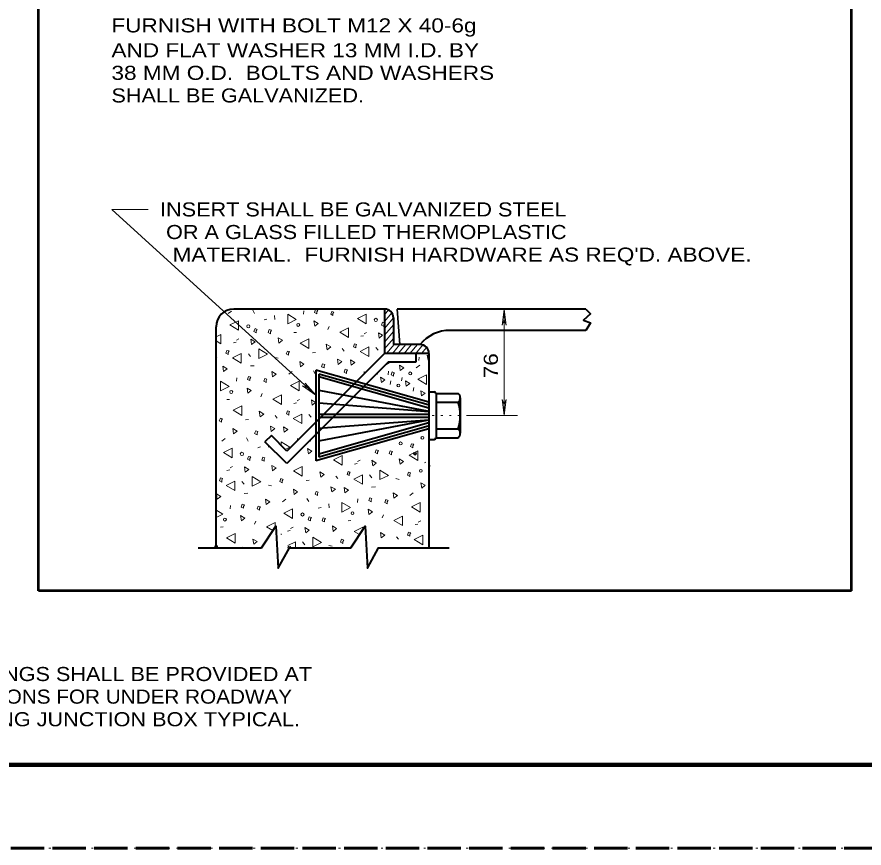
# Model space of a CAD drawing. Extents: x 312583 to 312854, y 144419 to 144597.
# Drawn here: x 312751.27 to 312797.02, y 144418.58 to 144463.44 of the extents above; entities that cross this region are included whole.
import ezdxf

# ---------------------------------------------------------------- set-up
doc = ezdxf.new("R2010")
doc.units = 0
doc.header["$LTSCALE"] = 0.3
doc.header["$PDMODE"] = 32
doc.header["$PDSIZE"] = 0.15
doc.linetypes.add('DOTTED', pattern=[1.5, 0.3, -1.2])
doc.linetypes.add('LONG_DASHED', pattern=[7.5, 6, -1.5])
doc.layers.add('1', color=7, linetype='Continuous', lineweight=13)
doc.layers.add('63', color=7, linetype='DOTTED', lineweight=13)

msp = doc.modelspace()

# ---------------------------------------------------------------- linework, layer by layer
at = {"layer": '1', "lineweight": 53}
for p, q in [((312796.3473, 144432.4767), (312796.3473, 144512.4926)), ((312752.4335, 144432.4767), (312752.4335, 144510.2401)), ((312796.3473, 144432.4767), (312752.4335, 144432.4767))]:
    msp.add_line(p, q, dxfattribs=at)
at = {"layer": '1'}
for p, q in [((312762.8669, 144447.5704), (312762.6829, 144447.4401)), ((312764.0169, 144447.6088), (312764.1013, 144447.4401)), ((312766.7463, 144447.3941), (312766.7693, 144447.5858)), ((312768.6936, 144447.6778), (312768.7013, 144447.6394)), ((312768.7013, 144447.6394), (312768.7549, 144447.6778)), ((312771.3463, 144447.6318), (312771.1316, 144447.3711)), ((312777.5793, 144447.6778), (312777.4719, 144446.8114)), ((312777.5793, 144441.9278), (312777.5793, 144447.6778)), ((312777.5793, 144447.6778), (312777.6866, 144446.8114)), ((312764.6226, 144447.0874), (312764.7683, 144447.1258)), ((312765.1823, 144447.3251), (312765.2053, 144447.1104)), ((312771.5226, 144447.4708), (312771.1316, 144447.0031)), ((312771.6069, 144447.2024), (312771.1316, 144446.6351)), ((312768.1416, 144446.7348), (312768.0649, 144446.5661)), ((312771.0933, 144446.8498), (312771.1316, 144446.9188)), ((312771.6069, 144446.8268), (312771.1316, 144446.2671)), ((312777.4719, 144446.8114), (312777.5793, 144447.0874)), ((312777.6866, 144446.8114), (312777.5793, 144447.0874)), ((312766.2326, 144446.4128), (312766.3783, 144446.4204)), ((312769.8513, 144446.2058), (312769.9969, 144446.2364)), ((312770.0199, 144446.3361), (312770.1503, 144446.4128)), ((312771.6069, 144446.4588), (312771.1316, 144445.8991)), ((312762.0313, 144445.9604), (312762.2919, 144445.7994)), ((312762.9666, 144445.8608), (312763.1123, 144445.8914)), ((312763.1353, 144445.9911), (312763.2579, 144446.0678)), ((312771.6069, 144446.0908), (312771.1316, 144445.5234)), ((312771.6453, 144445.7611), (312771.2389, 144445.2858)), ((312771.9596, 144445.7611), (312771.5533, 144445.2858)), ((312772.2739, 144445.7611), (312771.8676, 144445.2858)), ((312772.5883, 144445.7611), (312772.1819, 144445.2858)), ((312772.9026, 144445.7611), (312772.4963, 144445.2858)), ((312773.1939, 144445.7381), (312772.8106, 144445.2858)), ((312767.2446, 144445.3164), (312767.3979, 144445.3318)), ((312768.8469, 144445.5541), (312768.9543, 144445.4084)), ((312770.6563, 144445.6078), (312770.7789, 144445.4544)), ((312771.1316, 144445.4084), (312771.1239, 144445.4084)), ((312773.4009, 144445.6078), (312773.1249, 144445.2858)), ((312773.5159, 144445.3778), (312773.4393, 144445.2858)), ((312762.0313, 144445.1171), (312762.0619, 144445.0634)), ((312763.7716, 144445.2628), (312763.8943, 144445.1094)), ((312765.1976, 144445.0711), (312765.3739, 144445.0328)), ((312770.7713, 144444.9561), (312770.8019, 144444.9561)), ((312772.9716, 144444.9024), (312772.9946, 144445.0864)), ((312773.4776, 144444.9101), (312773.5313, 144444.9484)), ((312763.8866, 144444.6111), (312764.0936, 144444.6188)), ((312773.0253, 144444.6494), (312772.8413, 144444.5114)), ((312763.1276, 144443.7831), (312763.1506, 144443.9671)), ((312766.1329, 144444.3044), (312765.9566, 144444.1664)), ((312767.2829, 144444.3428), (312767.3749, 144444.1741)), ((312770.0199, 144444.1741), (312770.0353, 144444.3121)), ((312771.3156, 144444.1358), (312771.3386, 144444.3274)), ((312772.0516, 144443.7984), (312772.0746, 144443.9901)), ((312766.7003, 144443.5301), (312766.9763, 144443.4228)), ((312767.4133, 144443.0241), (312766.7003, 144443.5301)), ((312766.8459, 144443.6834), (312766.9763, 144443.4228)), ((312767.4133, 144443.0241), (312766.8459, 144443.6834)), ((312771.4383, 144443.6144), (312771.4613, 144443.8061)), ((312772.6803, 144443.2541), (312772.7033, 144443.4458)), ((312764.5229, 144443.1161), (312764.4463, 144442.9474)), ((312762.6139, 144442.8018), (312762.7596, 144442.8018)), ((312766.2326, 144442.5871), (312766.3783, 144442.6178)), ((312766.4089, 144442.7251), (312766.5316, 144442.7941)), ((312777.4719, 144442.7941), (312777.5793, 144442.5181)), ((312777.5793, 144441.9278), (312777.4719, 144442.7941)), ((312777.6866, 144442.7941), (312777.5793, 144442.5181)), ((312777.5793, 144441.9278), (312777.6866, 144442.7941)), ((312767.6049, 144442.2498), (312767.6049, 144441.7591)), ((312763.6259, 144441.6978), (312763.7793, 144441.7131)), ((312765.2283, 144441.9354), (312765.3356, 144441.7898)), ((312767.0376, 144441.9891), (312767.1603, 144441.8358)), ((312775.6473, 144441.9278), (312778.3076, 144441.9278)), ((312767.1603, 144441.3374), (312767.1909, 144441.3374)), ((312763.6719, 144440.7241), (312763.7563, 144440.5554)), ((312766.4089, 144440.5554), (312766.4243, 144440.6934)), ((312762.5219, 144440.6858), (312762.3379, 144440.5478)), ((312764.2776, 144440.1951), (312764.4233, 144440.2411)), ((312764.8526, 144440.3408), (312764.8603, 144440.2258)), ((312765.5503, 144440.5094), (312765.5503, 144440.3254)), ((312771.1699, 144440.5478), (312771.3156, 144440.5861)), ((312769.5063, 144439.3134), (312769.6519, 144439.3441)), ((312769.6749, 144439.4514), (312769.8053, 144439.5204)), ((312773.3549, 144439.4131), (312773.2936, 144439.3824)), ((312762.6139, 144438.9684), (312762.7673, 144438.9991)), ((312762.7903, 144439.1064), (312762.9129, 144439.1754)), ((312773.5696, 144439.1754), (312773.5696, 144439.2444)), ((312766.8996, 144438.4241), (312767.0529, 144438.4394)), ((312768.5019, 144438.6618), (312768.6093, 144438.5238)), ((312770.3113, 144438.7231), (312770.4339, 144438.5621)), ((312771.7449, 144438.5238), (312771.9136, 144438.4854)), ((312763.4189, 144438.3781), (312763.5493, 144438.2171)), ((312764.8526, 144438.1788), (312765.0213, 144438.1404)), ((312770.4263, 144438.0638), (312770.6409, 144438.0791)), ((312763.5416, 144437.7188), (312763.7486, 144437.7341)), ((312772.6803, 144437.7571), (312772.4963, 144437.6191)), ((312762.7826, 144436.8908), (312762.8056, 144437.0748)), ((312765.7879, 144437.4121), (312765.6116, 144437.2741)), ((312766.9379, 144437.4504), (312767.0299, 144437.2818)), ((312768.1109, 144437.1591), (312768.1339, 144436.9521)), ((312769.6673, 144437.2358), (312769.6903, 144437.4274)), ((312767.5513, 144436.9291), (312767.6969, 144436.9674)), ((312771.0626, 144436.5764), (312770.9936, 144436.4078)), ((312764.1779, 144436.2314), (312764.1013, 144436.0628)), ((312769.1536, 144436.2544), (312769.2993, 144436.2621)), ((312772.9486, 144436.1778), (312773.0789, 144436.2468)), ((312762.2689, 144435.9094), (312762.4146, 144435.9171)), ((312765.8876, 144435.6948), (312766.0333, 144435.7254)), ((312766.0563, 144435.8328), (312766.1866, 144435.9018)), ((312772.7799, 144436.0398), (312772.9256, 144436.0704)), ((312771.7756, 144435.3881), (312771.8829, 144435.2501)), ((312762.0313, 144434.8591), (312762.0313, 144434.8668)), ((312763.2809, 144434.8131), (312763.4343, 144434.8208)), ((312766.6926, 144435.1044), (312766.8153, 144434.9434)), ((312768.1263, 144434.9128), (312768.2949, 144434.8744))]:
    msp.add_line(p, q, dxfattribs=at)
at = {"layer": '1', "lineweight": 40}
for p, q in [((312771.1316, 144447.6778), (312762.9819, 144447.6778)), ((312771.1316, 144447.6778), (312771.1316, 144445.2858)), ((312782.0029, 144447.6778), (312771.8139, 144447.6778)), ((312771.6069, 144447.2024), (312771.6069, 144445.7611)), ((312762.0236, 144446.7194), (312762.0236, 144434.7978)), ((312782.0029, 144446.5201), (312774.6813, 144446.5201)), ((312773.0483, 144445.7611), (312771.6069, 144445.7611)), ((312771.1316, 144445.2858), (312765.8569, 144440.0111)), ((312773.5236, 144445.2858), (312771.1316, 144445.2858)), ((312772.8106, 144445.2858), (312772.8106, 144444.8028)), ((312773.5236, 144445.2858), (312773.5236, 144434.7978)), ((312771.3309, 144444.8028), (312765.8569, 144439.3364)), ((312767.4133, 144444.3734), (312767.4133, 144439.4821)), ((312773.5236, 144442.6484), (312767.4133, 144444.3734)), ((312772.8106, 144444.8028), (312771.3309, 144444.8028)), ((312767.5819, 144444.1664), (312767.5819, 144439.6891)), ((312773.4853, 144442.5028), (312767.5819, 144444.1664)), ((312773.5236, 144442.3264), (312767.5819, 144444.0131)), ((312767.5819, 144443.2924), (312773.5236, 144442.1578)), ((312773.5236, 144443.2081), (312773.8073, 144443.2081)), ((312773.9069, 144443.1238), (312775.0953, 144443.1238)), ((312773.9069, 144443.1084), (312773.9069, 144440.7318)), ((312767.5819, 144442.6178), (312773.5236, 144442.1501)), ((312773.9069, 144442.6484), (312775.0953, 144442.6484)), ((312775.2179, 144442.8861), (312775.2179, 144440.9771)), ((312767.5819, 144442.0044), (312773.5236, 144442.0044)), ((312767.5819, 144441.8511), (312773.5236, 144441.8511)), ((312767.5819, 144441.2454), (312773.5236, 144441.7054)), ((312767.5819, 144440.5708), (312773.5236, 144441.6978)), ((312773.5236, 144441.2071), (312767.4133, 144439.4821)), ((312773.5236, 144441.5291), (312767.5819, 144439.8501)), ((312773.4853, 144441.3604), (312767.5819, 144439.6891)), ((312773.9069, 144441.2071), (312775.0953, 144441.2071)), ((312765.0136, 144440.8544), (312764.6686, 144440.5171)), ((312765.8569, 144440.0111), (312765.0136, 144440.8544)), ((312773.9069, 144440.7318), (312775.0953, 144440.7318)), ((312765.8569, 144439.3364), (312764.6686, 144440.5171)), ((312773.5236, 144440.6398), (312773.8073, 144440.6398)), ((312761.0576, 144434.7978), (312764.4846, 144434.7978)), ((312765.9873, 144434.7978), (312769.3069, 144434.7978))]:
    msp.add_line(p, q, dxfattribs=at)
at = {"layer": '1', "lineweight": 35}
msp.add_line((312771.9443, 144445.7611), (312771.8139, 144447.6778), dxfattribs=at)
at = {"layer": '1', "linetype": 'DOTTED'}
msp.add_line((312775.6473, 144441.9278), (312773.5236, 144441.9278), dxfattribs=at)
at = {"layer": '1', "lineweight": 158}
msp.add_line((312616.5, 144423.0846), (312849, 144423.0846), dxfattribs=at)
at = {"layer": '1', "linetype": 'LONG_DASHED', "lineweight": 60}
msp.add_line((312851.75, 144418.5846), (312583.526, 144418.5846), dxfattribs=at)
at = {"layer": '1'}
for points in [[(312758.3589, 144453.0444), (312756.4039, 144453.0444), (312767.4133, 144443.0241)], [(312771.1316, 144446.9264), (312771.0166, 144446.9648), (312770.9629, 144446.8114), (312771.0933, 144446.7424), (312771.0933, 144446.8498)], [(312762.2919, 144445.7994), (312762.2919, 144446.3131), (312762.0313, 144446.1828)], [(312773.5313, 144445.1401), (312773.4316, 144445.1938), (312773.4776, 144444.9101)], [(312771.3233, 144444.7951), (312771.3769, 144444.7568), (312771.1776, 144444.6494)], [(312770.7023, 144444.1741), (312770.7483, 144444.1588), (312770.7483, 144444.2201)], [(312765.7649, 144440.1031), (312766.0179, 144440.2258), (312765.5503, 144440.5094)], [(312767.0913, 144440.5631), (312767.1296, 144440.5401), (312767.1296, 144440.6014)], [(312762.0313, 144436.4231), (312762.3993, 144436.6148), (312762.0236, 144436.8371)], [(312765.2206, 144435.9018), (312765.2206, 144436.1548), (312764.7529, 144435.9171), (312765.0903, 144435.7178)], [(312769.9586, 144435.7714), (312769.9586, 144435.9018), (312769.4909, 144435.6718), (312769.7746, 144435.5031)], [(312765.5503, 144435.5031), (312765.5656, 144435.5184), (312765.5349, 144435.5338)], [(312766.3093, 144434.8054), (312766.3093, 144435.1198), (312765.9106, 144434.9204)], [(312771.5303, 144434.8054), (312771.5073, 144434.8131), (312771.5073, 144434.8054)]]:
    msp.add_lwpolyline(points, dxfattribs=at)
for points in [[(312767.4746, 144447.5321), (312767.5206, 144447.6164), (312767.4056, 144447.6471), (312767.3443, 144447.4938), (312767.4746, 144447.4248)], [(312765.8953, 144447.4018), (312765.8953, 144446.8804), (312766.3629, 144447.1181)], [(312768.3409, 144447.4324), (312768.3946, 144447.5091), (312768.2719, 144447.5474), (312768.2183, 144447.3941), (312768.3409, 144447.3251)], [(312770.1273, 144446.8804), (312770.1273, 144447.3941), (312769.6596, 144447.1641)], [(312763.2349, 144446.5354), (312763.2349, 144447.0491), (312762.7673, 144446.8191)], [(312767.3596, 144446.7501), (312767.5513, 144446.8958), (312767.3136, 144447.0338)], [(312769.1843, 144446.1444), (312769.1843, 144446.6581), (312768.7166, 144446.4281)], [(312764.2009, 144446.5048), (312764.2469, 144446.5814), (312764.1319, 144446.6198), (312764.0706, 144446.4664), (312764.2009, 144446.3974)], [(312764.9676, 144446.4511), (312765.0136, 144446.5354), (312764.8986, 144446.5661), (312764.8373, 144446.4128), (312764.9676, 144446.3438)], [(312770.8326, 144446.1138), (312771.0243, 144446.2594), (312770.7943, 144446.3974)], [(312763.9479, 144445.7688), (312764.1396, 144445.9144), (312763.9019, 144446.0524)], [(312765.4199, 144445.8454), (312765.6193, 144445.9911), (312765.3816, 144446.1291)], [(312767.0299, 144445.5541), (312767.0299, 144446.0678), (312766.5623, 144445.8301)], [(312768.0266, 144445.4851), (312768.2183, 144445.6308), (312767.9806, 144445.7764)], [(312769.5753, 144445.6768), (312769.6213, 144445.7611), (312769.4986, 144445.7994), (312769.4449, 144445.6461), (312769.5753, 144445.5771)], [(312762.6829, 144445.3318), (312762.7289, 144445.4161), (312762.6139, 144445.4468), (312762.5526, 144445.3011), (312762.6829, 144445.2244)], [(312763.3883, 144444.7644), (312763.3883, 144445.2858), (312762.9206, 144445.0481)], [(312764.3313, 144445.5234), (312764.3313, 144445.0098), (312764.7989, 144445.2398)], [(312765.9489, 144445.2934), (312765.9949, 144445.3778), (312765.8799, 144445.4084), (312765.8186, 144445.2628), (312765.9489, 144445.1861)], [(312770.2729, 144445.1094), (312770.2729, 144445.6308), (312769.8053, 144445.3931)], [(312766.5853, 144444.5651), (312766.7769, 144444.7108), (312766.5469, 144444.8488)], [(312768.6169, 144444.6878), (312768.8163, 144444.8411), (312768.5786, 144444.9791)], [(312769.3223, 144444.6494), (312769.5216, 144444.7951), (312769.2839, 144444.9408)], [(312762.4376, 144444.3044), (312762.6293, 144444.4501), (312762.3993, 144444.5958)], [(312767.8579, 144444.6034), (312767.9039, 144444.6878), (312767.7813, 144444.7184), (312767.7276, 144444.5651), (312767.8579, 144444.4961)], [(312769.0769, 144444.3044), (312769.1229, 144444.3888), (312769.0003, 144444.4271), (312768.9466, 144444.2738), (312769.0769, 144444.2048)], [(312771.9749, 144444.3658), (312772.1666, 144444.5114), (312771.9289, 144444.6494)], [(312763.8559, 144443.9134), (312763.9019, 144443.9978), (312763.7869, 144444.0361), (312763.7256, 144443.8828), (312763.8559, 144443.8138)], [(312764.7299, 144443.8138), (312764.7759, 144443.8981), (312764.6533, 144443.9288), (312764.5996, 144443.7831), (312764.7299, 144443.7064)], [(312765.0826, 144444.0208), (312765.2743, 144444.1664), (312765.0443, 144444.3044)], [(312770.9553, 144443.7141), (312771.1469, 144443.8598), (312770.9169, 144443.9978)], [(312771.6146, 144444.1588), (312771.6606, 144444.2431), (312771.5456, 144444.2814), (312771.4843, 144444.1281), (312771.6146, 144444.0591)], [(312773.4009, 144443.6144), (312773.4009, 144444.1281), (312772.9333, 144443.8904)], [(312762.2766, 144443.7831), (312762.2766, 144443.2694), (312762.7443, 144443.4994)], [(312766.5086, 144443.2618), (312766.5086, 144443.7831), (312766.0409, 144443.5454)], [(312772.2969, 144443.5148), (312772.4886, 144443.6604), (312772.2586, 144443.8061)], [(312763.7409, 144443.1314), (312763.9326, 144443.2771), (312763.7026, 144443.4151)], [(312765.5656, 144442.5258), (312765.5656, 144443.0394), (312765.0979, 144442.8094)], [(312773.1249, 144442.9858), (312773.3166, 144443.1314), (312773.0866, 144443.2694)], [(312767.2139, 144442.4951), (312767.4056, 144442.6408), (312767.1756, 144442.7788)], [(312763.4113, 144441.9354), (312763.4113, 144442.4491), (312762.9436, 144442.2114)], [(312764.4079, 144441.8664), (312764.5996, 144442.0121), (312764.3619, 144442.1578)], [(312765.9566, 144442.0658), (312766.0026, 144442.1424), (312765.8876, 144442.1808), (312765.8263, 144442.0274), (312765.9566, 144441.9584)], [(312762.3303, 144441.6748), (312762.3763, 144441.7591), (312762.2613, 144441.7898), (312762.1999, 144441.6441), (312762.3303, 144441.5674)], [(312766.6543, 144441.4984), (312766.6543, 144442.0121), (312766.1866, 144441.7744)], [(312762.9666, 144440.9464), (312763.1659, 144441.0921), (312762.9283, 144441.2301)], [(312764.9983, 144441.0768), (312765.1976, 144441.2224), (312764.9599, 144441.3604)], [(312765.7113, 144441.0384), (312765.9029, 144441.1764), (312765.6653, 144441.3221)], [(312764.2393, 144440.9848), (312764.2853, 144441.0691), (312764.1703, 144441.1074), (312764.1089, 144440.9541), (312764.2393, 144440.8851)], [(312772.6573, 144440.2948), (312772.7033, 144440.3791), (312772.5883, 144440.4098), (312772.5346, 144440.2564), (312772.6573, 144440.1874)], [(312762.8899, 144439.6508), (312762.8899, 144440.1644), (312762.4223, 144439.9268)], [(312767.0146, 144439.8578), (312767.2063, 144440.0034), (312766.9686, 144440.1491)], [(312770.7483, 144439.9574), (312770.7943, 144440.0418), (312770.6716, 144440.0801), (312770.6179, 144439.9268), (312770.7483, 144439.8578)], [(312771.5073, 144439.9114), (312771.5533, 144439.9881), (312771.4383, 144440.0264), (312771.3846, 144439.8731), (312771.5073, 144439.8041)], [(312772.9333, 144439.5051), (312772.9333, 144440.0188), (312772.4656, 144439.7888)], [(312763.8559, 144439.6124), (312763.9019, 144439.6968), (312763.7869, 144439.7274), (312763.7256, 144439.5741), (312763.8559, 144439.5051)], [(312764.6226, 144439.5664), (312764.6686, 144439.6431), (312764.5536, 144439.6814), (312764.4923, 144439.5281), (312764.6226, 144439.4591)], [(312768.8393, 144439.2598), (312768.8393, 144439.7734), (312768.3716, 144439.5358)], [(312770.4876, 144439.2214), (312770.6793, 144439.3671), (312770.4493, 144439.5128)], [(312771.9673, 144439.2981), (312772.1589, 144439.4438), (312771.9213, 144439.5894)], [(312763.5953, 144438.8764), (312763.7946, 144439.0221), (312763.5569, 144439.1678)], [(312765.0749, 144438.9531), (312765.2666, 144439.0988), (312765.0366, 144439.2368)], [(312766.6849, 144438.6618), (312766.6849, 144439.1754), (312766.2173, 144438.9454)], [(312767.6816, 144438.6004), (312767.8733, 144438.7461), (312767.6356, 144438.8841)], [(312769.2226, 144438.7921), (312769.2686, 144438.8688), (312769.1536, 144438.9071), (312769.0999, 144438.7538), (312769.2226, 144438.6848)], [(312770.8786, 144438.9838), (312770.8786, 144438.4701), (312771.3463, 144438.7001)], [(312772.4886, 144438.7461), (312772.5346, 144438.8304), (312772.4196, 144438.8688), (312772.3659, 144438.7154), (312772.4886, 144438.6464)], [(312762.3379, 144438.4471), (312762.3839, 144438.5238), (312762.2689, 144438.5621), (312762.2076, 144438.4088), (312762.3379, 144438.3398)], [(312763.9863, 144438.6388), (312763.9863, 144438.1174), (312764.4539, 144438.3551)], [(312765.6039, 144438.4011), (312765.6499, 144438.4854), (312765.5349, 144438.5238), (312765.4736, 144438.3704), (312765.6039, 144438.3014)], [(312769.9279, 144438.2248), (312769.9279, 144438.7384), (312769.4603, 144438.5008)], [(312763.0356, 144437.8798), (312763.0356, 144438.3934), (312762.5679, 144438.1558)], [(312766.2403, 144437.6728), (312766.4319, 144437.8184), (312766.2019, 144437.9564)], [(312768.2719, 144437.8031), (312768.4713, 144437.9488), (312768.2336, 144438.0868)], [(312768.9773, 144437.7648), (312769.1766, 144437.9104), (312768.9389, 144438.0484)], [(312773.1326, 144438.0178), (312773.3243, 144438.1634), (312773.0866, 144438.3014)], [(312762.0926, 144437.4198), (312762.2843, 144437.5654), (312762.0543, 144437.7034)], [(312767.5053, 144437.7188), (312767.5513, 144437.7954), (312767.4363, 144437.8338), (312767.3826, 144437.6804), (312767.5053, 144437.6114)], [(312770.4033, 144437.3738), (312770.4493, 144437.4504), (312770.3266, 144437.4888), (312770.2729, 144437.3354), (312770.4033, 144437.2664)], [(312771.6299, 144437.4734), (312771.8216, 144437.6191), (312771.5839, 144437.7648)], [(312763.5109, 144437.0288), (312763.5569, 144437.1054), (312763.4419, 144437.1438), (312763.3806, 144436.9904), (312763.5109, 144436.9214)], [(312764.3773, 144436.9291), (312764.4309, 144437.0058), (312764.3083, 144437.0441), (312764.2546, 144436.8908), (312764.3773, 144436.8218)], [(312764.7376, 144437.1284), (312764.9293, 144437.2741), (312764.6993, 144437.4198)], [(312768.8239, 144437.2358), (312768.8239, 144436.7221), (312769.2916, 144436.9598)], [(312771.2696, 144437.2741), (312771.3156, 144437.3508), (312771.2006, 144437.3891), (312771.1393, 144437.2358), (312771.2696, 144437.1668)], [(312773.0559, 144436.7221), (312773.0559, 144437.2358), (312772.5883, 144437.0058)], [(312766.1636, 144436.3771), (312766.1636, 144436.8908), (312765.6959, 144436.6608)], [(312770.2806, 144436.5918), (312770.4799, 144436.7374), (312770.2423, 144436.8754)], [(312763.3959, 144436.2468), (312763.5876, 144436.3924), (312763.3499, 144436.5304)], [(312767.1296, 144436.3464), (312767.1756, 144436.4231), (312767.0606, 144436.4614), (312766.9993, 144436.3081), (312767.1296, 144436.2391)], [(312767.8886, 144436.2928), (312767.9423, 144436.3694), (312767.8196, 144436.4078), (312767.7659, 144436.2544), (312767.8886, 144436.1854)], [(312772.1053, 144435.9861), (312772.1053, 144436.4998), (312771.6376, 144436.2621)], [(312766.8689, 144435.6028), (312767.0606, 144435.7484), (312766.8306, 144435.8941)], [(312768.3486, 144435.6794), (312768.5403, 144435.8328), (312768.3103, 144435.9708)], [(312763.0663, 144435.0431), (312763.0663, 144435.5568), (312762.5986, 144435.3268)], [(312764.0629, 144434.9818), (312764.2546, 144435.1274), (312764.0169, 144435.2654)], [(312767.2599, 144435.3651), (312767.2599, 144434.8514), (312767.7276, 144435.0814)], [(312768.8776, 144435.1351), (312768.9236, 144435.2118), (312768.8009, 144435.2501), (312768.7473, 144435.0968), (312768.8776, 144435.0278)], [(312770.9476, 144435.3268), (312771.1393, 144435.4724), (312770.9093, 144435.6104)], [(312772.4963, 144435.5184), (312772.5423, 144435.6028), (312772.4273, 144435.6334), (312772.3736, 144435.4801), (312772.4963, 144435.4111)], [(312773.2016, 144434.9511), (312773.2016, 144435.4648), (312772.7339, 144435.2348)]]:
    msp.add_lwpolyline(points, close=True, dxfattribs=at)
at = {"layer": '1', "lineweight": 40}
for points in [[(312782.0029, 144447.6778), (312782.2559, 144447.4171), (312781.8726, 144447.0798), (312782.2559, 144446.9341), (312782.0029, 144446.5201)], [(312764.4846, 144434.7978), (312765.2589, 144435.9631), (312765.3893, 144433.6861), (312765.9873, 144434.7978)], [(312769.3069, 144434.7978), (312770.0813, 144435.9631), (312770.2116, 144433.6861), (312770.8096, 144434.7978), (312774.6123, 144434.7978)]]:
    msp.add_lwpolyline(points, dxfattribs=at)
at = {"layer": '1'}
for centre, radius in [((312770.6579, 144447.0938), 0.0865), ((312763.769, 144446.7482), 0.0865), ((312766.4679, 144446.8192), 0.0784), ((312772.5181, 144444.2027), 0.0784), ((312771.876, 144443.5491), 0.0784), ((312762.8506, 144443.202), 0.0784), ((312773.1717, 144440.7258), 0.0784), ((312771.9968, 144440.4249), 0.0784), ((312763.4234, 144439.8593), 0.0865), ((312773.0854, 144438.9472), 0.0784), ((312766.695, 144436.5876), 0.0865), ((312769.3939, 144436.6587), 0.0784), ((312762.505, 144436.3131), 0.0784)]:
    msp.add_circle(centre, radius, dxfattribs=at)
at = {"layer": '1', "lineweight": 40}
for centre, radius, start, end in [((312762.9839, 144446.7214), 0.9583, 90, 180), ((312771.1297, 144447.2005), 0.4792, 0, 90), ((312774.6289, 144444.4891), 2.0316, 88.63097, 141.1667), ((312773.0464, 144445.2839), 0.4792, 0, 90), ((312773.8092, 144443.1104), 0.0958, 0, 90), ((312774.9151, 144442.888), 0.3009, 307.23717, 52.76282), ((312772.983, 144441.9297), 2.2331, 341.22405, 18.77595), ((312774.9151, 144440.9714), 0.3009, 307.23718, 52.76283), ((312773.8092, 144440.7337), 0.0958, 270, 0)]:
    msp.add_arc(centre, radius, start, end, dxfattribs=at)
at = {"layer": '1'}
for p in [(312772.7723, 144439.8731), (312762.0313, 144434.8668), (312765.9873, 144434.8054)]:
    msp.add_point(p, dxfattribs=at)
at = {"layer": '63'}
msp.add_lwpolyline([(312601.2, 144418.5846), (312853.5, 144418.5846), (312853.5, 144596.7846)], dxfattribs=at)

# ---------------------------------------------------------------- texts
at = {"layer": '1'}
for s, width, p in [('FURNISH WITH BOLT M12 X 40-6g', 1.2, (312756.3743, 144462.6094)), ('AND FLAT WASHER 13 MM I.D. BY', 1.2, (312756.3786, 144461.2676)), ('38 MM O.D.  BOLTS AND WASHERS', 1.2, (312756.3786, 144460.0476)), ('SHALL BE GALVANIZED.', 1.15, (312756.3786, 144458.8276)), ('INSERT SHALL BE GALVANIZED STEEL', 1.15, (312759.0029, 144452.6754)), (' OR A GLASS FILLED THERMOPLASTIC', 1.15, (312759.0029, 144451.4554)), ("  MATERIAL.  FURNISH HARDWARE AS REQ'D. ABOVE.", 1.2, (312759.0029, 144450.2354)), ('ADDITIONAL OPENINGS SHALL BE PROVIDED AT', 1.15, (312739.548, 144427.5981)), ('APPROVED ELEVATIONS FOR UNDER ROADWAY', 1.1, (312739.548, 144426.3781)), ('CONDUITS ENTERING JUNCTION BOX TYPICAL.', 1.15, (312739.548, 144425.1581))]:
    msp.add_text(s, height=0.76, dxfattribs=dict(at, width=width)).set_placement(p)
at = {"layer": '1', "width": 1.2}
msp.add_text('76 ', height=0.76, rotation=90, dxfattribs=at).set_placement((312777.248, 144443.9403))

doc.saveas('drawing.dxf')
